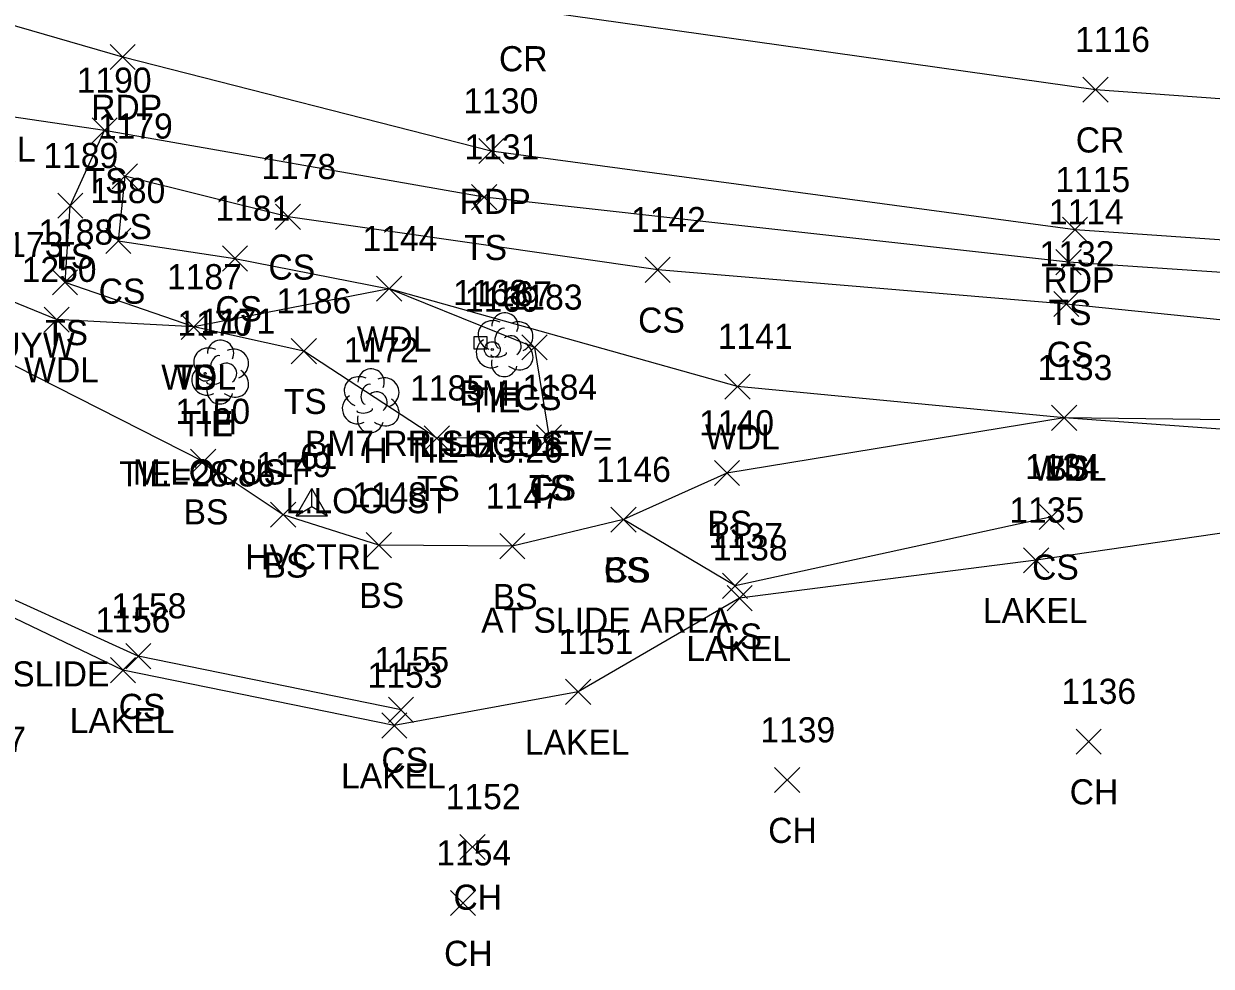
# Model space of a CAD drawing. Extents: x 1401404 to 1403982, y 557481 to 559873.
# Drawn here: x 1403353.7 to 1403448.2, y 558518.7 to 558593.7 of the extents above; entities that cross this region are included whole.
import ezdxf

# ---------------------------------------------------------------- set-up
doc = ezdxf.new("R2010")
doc.units = 0
for name, color, linetype in [('C_A', 7, 'Continuous'), ('C_C', 7, 'Continuous'), ('C_I', 7, 'Continuous'), ('CBP', 7, 'Continuous'), ('CPBM', 7, 'Continuous'), ('CPSM', 7, 'Continuous'), ('L_A', 7, 'Continuous'), ('L_C', 7, 'Continuous'), ('L_I', 7, 'Continuous'), ('L_TIC', 7, 'Continuous'), ('LAWA', 7, 'Continuous'), ('LAWE', 7, 'Continuous'), ('LELB', 7, 'Continuous'), ('LTD', 7, 'Continuous'), ('P_A', 7, 'Continuous'), ('P_I', 7, 'Continuous'), ('P_TIC', 7, 'Continuous'), ('PET', 7, 'Continuous'), ('PRC', 7, 'Continuous'), ('U_A', 7, 'Continuous'), ('U_I', 7, 'Continuous')]:
    doc.layers.add(name, color=color, linetype=linetype)

msp = doc.modelspace()

# ---------------------------------------------------------------- linework, layer by layer
at = {"layer": 'CBP'}
for centre, radius in [((1403391.006, 558567.757), 0.625), ((1403391.006, 558567.757), 0.0833), ((1403368.162, 558565.858), 0.625), ((1403368.162, 558565.858), 0.0833)]:
    msp.add_circle(centre, radius, dxfattribs=at)
at = {"layer": 'CPBM'}
for p, q in [((1403389.564, 558567.797), (1403389.564, 558568.797)), ((1403389.564, 558568.797), (1403390.564, 558568.797)), ((1403390.066, 558568.298), (1403390.066, 558568.298)), ((1403390.066, 558568.298), (1403390.066, 558568.298)), ((1403390.564, 558568.797), (1403390.564, 558567.797)), ((1403390.564, 558567.797), (1403389.564, 558567.797))]:
    msp.add_line(p, q, dxfattribs=at)
at = {"layer": 'CPSM'}
for p, q in [((1403375.408, 558554.533), (1403376.658, 558556.698)), ((1403377.908, 558554.533), (1403376.658, 558556.698)), ((1403376.659, 558555.254), (1403376.658, 558556.698)), ((1403375.408, 558554.533), (1403376.659, 558555.254)), ((1403376.659, 558555.254), (1403376.659, 558555.254)), ((1403376.659, 558555.254), (1403377.908, 558554.533)), ((1403375.408, 558554.533), (1403377.908, 558554.533))]:
    msp.add_line(p, q, dxfattribs=at)
at = {"layer": 'L_TIC'}
for points in [[(1403359.169, 558584.19), (1403361.169, 558586.19)], [(1403361.169, 558584.19), (1403359.169, 558586.19)], [(1403359.169, 558584.19), (1403361.169, 558586.19)], [(1403361.169, 558584.19), (1403359.169, 558586.19)], [(1403360.776, 558580.539), (1403362.776, 558582.539)], [(1403362.776, 558580.539), (1403360.776, 558582.539)], [(1403389.353, 558578.879), (1403391.353, 558580.879)], [(1403391.353, 558578.879), (1403389.353, 558580.879)], [(1403356.44, 558578.197), (1403358.44, 558580.197)], [(1403358.44, 558578.197), (1403356.44, 558580.197)], [(1403373.76, 558577.317), (1403375.76, 558579.317)], [(1403375.76, 558577.317), (1403373.76, 558579.317)], [(1403360.257, 558575.403), (1403362.257, 558577.403)], [(1403362.257, 558575.403), (1403360.257, 558577.403)], [(1403369.539, 558574.001), (1403371.539, 558576.001)], [(1403371.539, 558574.001), (1403369.539, 558576.001)], [(1403403.159, 558573.097), (1403405.159, 558575.097)], [(1403405.159, 558573.097), (1403403.159, 558575.097)], [(1403435.828, 558573.711), (1403437.828, 558575.711)], [(1403437.828, 558573.711), (1403435.828, 558575.711)], [(1403356.028, 558572.103), (1403358.028, 558574.103)], [(1403358.028, 558572.103), (1403356.028, 558574.103)], [(1403381.806, 558571.596), (1403383.806, 558573.596)], [(1403383.806, 558571.596), (1403381.806, 558573.596)], [(1403435.654, 558570.376), (1403437.654, 558572.376)], [(1403437.654, 558570.376), (1403435.654, 558572.376)], [(1403355.356, 558569.136), (1403357.356, 558571.136)], [(1403357.356, 558569.136), (1403355.356, 558571.136)], [(1403366.259, 558568.552), (1403368.259, 558570.552)], [(1403368.259, 558568.552), (1403366.259, 558570.552)], [(1403366.259, 558568.552), (1403368.259, 558570.552)], [(1403368.259, 558568.552), (1403366.259, 558570.552)], [(1403375.01, 558566.629), (1403377.01, 558568.629)], [(1403377.01, 558566.629), (1403375.01, 558568.629)], [(1403393.354, 558566.931), (1403395.354, 558568.931)], [(1403395.354, 558566.931), (1403393.354, 558568.931)], [(1403409.502, 558563.808), (1403411.502, 558565.808)], [(1403411.502, 558563.808), (1403409.502, 558565.808)], [(1403435.487, 558561.324), (1403437.487, 558563.324)], [(1403437.487, 558561.324), (1403435.487, 558563.324)], [(1403435.487, 558561.324), (1403437.487, 558563.324)], [(1403437.487, 558561.324), (1403435.487, 558563.324)], [(1403385.594, 558559.698), (1403387.594, 558561.698)], [(1403387.594, 558559.698), (1403385.594, 558561.698)], [(1403394.513, 558559.766), (1403396.513, 558561.766)], [(1403396.513, 558559.766), (1403394.513, 558561.766)], [(1403394.513, 558559.766), (1403396.513, 558561.766)], [(1403396.513, 558559.766), (1403394.513, 558561.766)], [(1403367.01, 558557.841), (1403369.01, 558559.841)], [(1403369.01, 558557.841), (1403367.01, 558559.841)], [(1403408.668, 558556.928), (1403410.668, 558558.928)], [(1403410.668, 558556.928), (1403408.668, 558558.928)], [(1403373.367, 558553.611), (1403375.367, 558555.611)], [(1403375.367, 558553.611), (1403373.367, 558555.611)], [(1403400.434, 558553.221), (1403402.434, 558555.221)], [(1403402.434, 558553.221), (1403400.434, 558555.221)], [(1403400.434, 558553.221), (1403402.434, 558555.221)], [(1403402.434, 558553.221), (1403400.434, 558555.221)], [(1403434.492, 558553.446), (1403436.492, 558555.446)], [(1403436.492, 558553.446), (1403434.492, 558555.446)], [(1403380.98, 558551.192), (1403382.98, 558553.192)], [(1403382.98, 558551.192), (1403380.98, 558553.192)], [(1403391.602, 558551.105), (1403393.602, 558553.105)], [(1403393.602, 558551.105), (1403391.602, 558553.105)], [(1403433.251, 558549.988), (1403435.251, 558551.988)], [(1403435.251, 558549.988), (1403433.251, 558551.988)], [(1403409.31, 558547.958), (1403411.31, 558549.958)], [(1403411.31, 558547.958), (1403409.31, 558549.958)], [(1403409.669, 558546.974), (1403411.669, 558548.974)], [(1403411.669, 558546.974), (1403409.669, 558548.974)], [(1403361.85, 558542.362), (1403363.85, 558544.362)], [(1403363.85, 558542.362), (1403361.85, 558544.362)], [(1403360.633, 558541.241), (1403362.633, 558543.241)], [(1403362.633, 558541.241), (1403360.633, 558543.241)], [(1403396.83, 558539.518), (1403398.83, 558541.518)], [(1403398.83, 558539.518), (1403396.83, 558541.518)], [(1403382.744, 558538.087), (1403384.744, 558540.087)], [(1403384.744, 558538.087), (1403382.744, 558540.087)], [(1403382.211, 558536.843), (1403384.211, 558538.843)], [(1403384.211, 558536.843), (1403382.211, 558538.843)], [(1403437.435, 558535.561), (1403439.435, 558537.561)], [(1403439.435, 558535.561), (1403437.435, 558537.561)], [(1403413.457, 558532.498), (1403415.457, 558534.498)], [(1403415.457, 558532.498), (1403413.457, 558534.498)], [(1403388.426, 558527.18), (1403390.426, 558529.18)], [(1403390.426, 558527.18), (1403388.426, 558529.18)], [(1403387.678, 558522.712), (1403389.678, 558524.712)], [(1403389.678, 558522.712), (1403387.678, 558524.712)]]:
    msp.add_lwpolyline(points, dxfattribs=at)
at = {"layer": 'LAWA'}
msp.add_lwpolyline([(1403486.896, 558558.65), (1403436.487, 558562.324), (1403410.502, 558564.808), (1403382.806, 558572.596), (1403367.259, 558569.552), (1403356.356, 558570.136), (1403328.829, 558581.386)], dxfattribs=at)
at = {"layer": 'LAWE'}
msp.add_lwpolyline([(1403696.339, 558534.541), (1403680.715, 558542.255), (1403669.402, 558548.582), (1403629.669, 558556.013), (1403603.5, 558551.349), (1403567.184, 558559.291), (1403520.129, 558560.765), (1403486.896, 558558.65), (1403434.251, 558550.988), (1403410.669, 558547.974), (1403397.83, 558540.518), (1403383.211, 558537.843), (1403361.633, 558542.241), (1403347.734, 558548.91), (1403330.859, 558557.202), (1403312.09, 558569.671), (1403266.361, 558595.501), (1403259.705, 558589.597), (1403257.895, 558590.945)], dxfattribs=at)
at = {"layer": 'LELB'}
for points in [[(1403567.19, 558568.672), (1403521.327, 558570.05), (1403484.768, 558571.485), (1403436.828, 558574.711), (1403390.353, 558579.879), (1403360.169, 558585.19), (1403345.928, 558587.285), (1403333.514, 558592.26), (1403317.515, 558600.618), (1403299.002, 558608.828), (1403282.939, 558617.965), (1403248.094, 558638.933), (1403217.119, 558660.936), (1403185.325, 558684.7), (1403148.792, 558715.456), (1403112.062, 558744.487), (1403074.233, 558776.659), (1403055.653, 558783.747), (1403043.183, 558796.215), (1403041.062, 558801.071)], [(1403395.513, 558560.766), (1403386.594, 558560.698), (1403376.01, 558567.629), (1403367.259, 558569.552), (1403357.028, 558573.103), (1403357.44, 558579.197), (1403360.169, 558585.19)], [(1403630.817, 558558.089), (1403605.037, 558560.568), (1403567.006, 558565.003), (1403521.817, 558567.095), (1403485.279, 558566.393), (1403436.654, 558571.376), (1403404.159, 558574.097), (1403374.76, 558578.317), (1403361.776, 558581.539), (1403361.257, 558576.403), (1403370.539, 558575.001)], [(1403725.577, 558523.668), (1403722.741, 558539.448), (1403706.557, 558549.474), (1403693.686, 558551.002), (1403674.49, 558552.834), (1403667, 558555.825), (1403630.817, 558558.089), (1403603.441, 558554.207), (1403567.497, 558561.8), (1403520.155, 558563.09), (1403486.237, 558561.719), (1403436.487, 558562.324), (1403409.668, 558557.928), (1403401.434, 558554.221), (1403392.602, 558552.105), (1403381.98, 558552.192), (1403374.367, 558554.611), (1403368.01, 558558.841), (1403339.846, 558573.137), (1403322.978, 558578.006)], [(1403370.539, 558575.001), (1403382.806, 558572.596)], [(1403394.354, 558567.931), (1403382.806, 558572.596)], [(1403383.744, 558539.087), (1403362.85, 558543.362), (1403348.357, 558549.947), (1403331.967, 558557.541), (1403320.969, 558571.115)], [(1403394.354, 558567.931), (1403395.513, 558560.766)], [(1403435.492, 558554.446), (1403410.31, 558548.958), (1403401.434, 558554.221)]]:
    msp.add_lwpolyline(points, dxfattribs=at)
at = {"layer": 'LTD'}
for p, q in [((1403391.966, 558568.192), (1403391.966, 558568.192)), ((1403391.966, 558568.192), (1403391.966, 558568.192)), ((1403369.347, 558566.014), (1403369.347, 558566.014)), ((1403369.347, 558566.014), (1403369.347, 558566.014)), ((1403381.314, 558563.731), (1403381.314, 558563.731)), ((1403381.314, 558563.731), (1403381.314, 558563.731))]:
    msp.add_line(p, q, dxfattribs=at)
for centre in [(1403392.013, 558569.626), (1403369.394, 558567.448), (1403381.361, 558565.165)]:
    msp.add_arc(centre, 1.047, 335.52715, 180.95627, dxfattribs=at)
for centre, major_axis, ratio, start_param, end_param in [((1403391.174, 558568.858), (1.21, -0.512), 0.895232, 1.570796, 4.712389), ((1403393.007, 558568.775), (-1.141, -0.483), 0.949671, 1.570796, 4.712389), ((1403391.757, 558568.65), (-0.208, -0.792), 0.645439, 3.141593, 6.283185), ((1403390.883, 558567.483), (0.584, -1.042), 0.959034, 3.141593, 6.283185), ((1403392.466, 558568.025), (-0.5, 0.667), 0.989748, 3.141593, 6.283185), ((1403392.966, 558567.358), (-1.09, 0.792), 0.841452, 1.570796, 4.712389), ((1403368.555, 558566.681), (1.21, -0.512), 0.895232, 1.570796, 4.712389), ((1403369.138, 558566.473), (-0.208, -0.792), 0.645439, 3.141593, 6.283185), ((1403370.388, 558566.598), (-1.141, -0.483), 0.949671, 1.570796, 4.712389), ((1403391.508, 558567.442), (-0.625, -0.083), 0.423636, 0, 3.141593), ((1403368.264, 558565.306), (0.584, -1.042), 0.959034, 3.141593, 6.283185), ((1403369.847, 558565.848), (-0.5, 0.667), 0.989748, 3.141593, 6.283185), ((1403391.966, 558566.692), (0.265, 1.061), 0.942809, 1.570796, 4.712389), ((1403370.347, 558565.181), (-1.09, 0.792), 0.841452, 1.570796, 4.712389), ((1403380.522, 558564.398), (1.21, -0.512), 0.895232, 1.570796, 4.712389), ((1403382.355, 558564.315), (-1.141, -0.483), 0.949671, 1.570796, 4.712389), ((1403369.347, 558564.514), (0.265, 1.061), 0.942809, 1.570796, 4.712389), ((1403368.889, 558565.264), (-0.625, -0.083), 0.423636, 0, 3.141593), ((1403381.105, 558564.189), (-0.208, -0.792), 0.645439, 3.141593, 6.283185), ((1403381.814, 558563.564), (-0.5, 0.667), 0.989748, 3.141593, 6.283185), ((1403380.231, 558563.023), (0.584, -1.042), 0.959034, 3.141593, 6.283185), ((1403382.314, 558562.898), (-1.09, 0.792), 0.841452, 1.570796, 4.712389), ((1403380.856, 558562.981), (-0.625, -0.083), 0.423636, 0, 3.141593), ((1403381.314, 558562.231), (0.265, 1.061), 0.942809, 1.570796, 4.712389)]:
    msp.add_ellipse(centre, major_axis=major_axis, ratio=ratio, start_param=start_param, end_param=end_param, dxfattribs=at)
at = {"layer": 'P_TIC'}
for points in [[(1403360.613, 558590.03), (1403362.613, 558592.03)], [(1403362.613, 558590.03), (1403360.613, 558592.03)], [(1403437.972, 558587.433), (1403439.972, 558589.433)], [(1403439.972, 558587.433), (1403437.972, 558589.433)], [(1403389.926, 558582.548), (1403391.926, 558584.548)], [(1403391.926, 558582.548), (1403389.926, 558584.548)], [(1403436.345, 558576.288), (1403438.345, 558578.288)], [(1403438.345, 558576.288), (1403436.345, 558578.288)]]:
    msp.add_lwpolyline(points, dxfattribs=at)
at = {"layer": 'PET'}
msp.add_lwpolyline([(1403567.323, 558571.161), (1403521.055, 558571.892), (1403485.08, 558573.953), (1403437.345, 558577.288), (1403390.926, 558583.548), (1403361.613, 558591.03), (1403321.823, 558602.545), (1403283.736, 558620.332), (1403244.193, 558645.3), (1403219.218, 558663.606), (1403205.442, 558672.119), (1403186.056, 558688.409), (1403150.644, 558718.107), (1403114.176, 558748.056), (1403076.198, 558780.032), (1403043.936, 558806.704), (1402997.13, 558841.767), (1402954.247, 558870.687), (1402915.87, 558893.532), (1402876.179, 558915.415), (1402801.328, 558955.205), (1402766.491, 558972.95)], dxfattribs=at)
at = {"layer": 'PRC'}
msp.add_lwpolyline([(1403567.874, 558582.773), (1403521.719, 558584.551), (1403486.229, 558585.007), (1403438.972, 558588.433), (1403393.102, 558594.896), (1403360.826, 558602.705), (1403288.915, 558631.603), (1403250.295, 558655.214), (1403225.89, 558672.347), (1403193.368, 558698.042), (1403157.152, 558726.964), (1403121.948, 558757.263), (1403083.224, 558789.984), (1403051.101, 558815.937), (1403004.274, 558851.49), (1402960.213, 558880.82), (1402921.635, 558903.817), (1402881.318, 558926.058), (1402807.323, 558964.726), (1402770.827, 558983.445)], dxfattribs=at)

# ---------------------------------------------------------------- texts
at = {"layer": 'C_A'}
for s, p in [('HVCTRL', (1403343.986, 558582.704)), ('BM', (1403388.381, 558563.298)), ('TIE', (1403389.085, 558562.757)), ('TIE', (1403366.241, 558560.858)), ('HVCTRL', (1403371.352, 558550.254))]:
    msp.add_text(s, height=2, dxfattribs=at).set_placement(p)
at = {"layer": 'C_C'}
for s, p in [('BM7 RR SIR ELEV=', (1403376.098, 558559.298)), ('TIE=43.26', (1403384.179, 558558.757)), ('TIE=28.86', (1403361.336, 558556.858))]:
    msp.add_text(s, height=2, dxfattribs=at).set_placement(p)
at = {"layer": 'C_I'}
for s, p in [('1168', (1403387.893, 558571.298)), ('1169', (1403388.825, 558570.757)), ('1170', (1403365.95, 558568.858)), ('61', (1403375.714, 558558.254))]:
    msp.add_text(s, height=2, dxfattribs=at).set_placement(p)
at = {"layer": 'L_A'}
for s, p in [('TS', (1403358.578, 558580.19)), ('TS', (1403358.578, 558580.19)), ('CS', (1403360.217, 558576.539)), ('TS', (1403388.763, 558574.879)), ('TS', (1403355.849, 558574.197)), ('CS', (1403373.201, 558573.317)), ('CS', (1403359.698, 558571.403)), ('CS', (1403368.98, 558570.001)), ('CS', (1403402.6, 558569.097)), ('TS', (1403435.237, 558569.711)), ('TS', (1403355.438, 558568.103)), ('WDL', (1403380.223, 558567.596)), ('CS', (1403435.095, 558566.376)), ('WDL', (1403353.774, 558565.136)), ('WDL', (1403364.676, 558564.552)), ('TS', (1403365.668, 558564.552)), ('TS', (1403374.419, 558562.629)), ('H', (1403391.399, 558563.192)), ('CS', (1403392.795, 558562.931)), ('H', (1403368.78, 558561.014)), ('WDL', (1403407.92, 558559.808)), ('H', (1403380.747, 558558.731)), ('WDL', (1403433.904, 558557.324)), ('BS', (1403434.928, 558557.324)), ('TS', (1403385.003, 558555.698)), ('TS', (1403393.922, 558555.766)), ('CS', (1403393.954, 558555.766)), ('BS', (1403366.451, 558553.841)), ('BS', (1403408.109, 558552.928)), ('BS', (1403372.808, 558549.611)), ('CS', (1403399.875, 558549.221)), ('BS', (1403399.875, 558549.221)), ('CS', (1403433.933, 558549.446)), ('BS', (1403380.421, 558547.192)), ('BS', (1403391.043, 558547.105)), ('LAKEL', (1403430.014, 558545.988)), ('CS', (1403408.751, 558543.958)), ('LAKEL', (1403406.433, 558542.974)), ('CS', (1403361.291, 558538.362)), ('LAKEL', (1403357.397, 558537.241)), ('LAKEL', (1403393.594, 558535.518)), ('CS', (1403382.185, 558534.087)), ('LAKEL', (1403378.974, 558532.843)), ('CH', (1403436.923, 558531.561)), ('CH', (1403412.945, 558528.498)), ('CH', (1403387.914, 558523.18)), ('CH', (1403387.167, 558518.712))]:
    msp.add_text(s, height=2, dxfattribs=at).set_placement(p)
at = {"layer": 'L_C'}
for s, p in [('L.LOCUST', (1403385.202, 558559.192)), ('M.LOCUST', (1403362.41, 558557.014)), ('L.LOCUST', (1403374.55, 558554.731)), ('AT SLIDE AREA', (1403390.119, 558545.221)), ('BEGIN HEAVY SLIDE', (1403333.948, 558540.947))]:
    msp.add_text(s, height=2, dxfattribs=at).set_placement(p)
at = {"layer": 'L_I'}
for s, p in [('1190', (1403357.956, 558588.19)), ('1190', (1403357.956, 558588.19)), ('1179', (1403359.642, 558584.539)), ('1131', (1403388.794, 558582.879)), ('1189', (1403355.306, 558582.197)), ('1178', (1403372.634, 558581.317)), ('1180', (1403359.045, 558579.403)), ('1181', (1403368.98, 558578.001)), ('1114', (1403435.269, 558577.711)), ('1142', (1403402.033, 558577.097)), ('1188', (1403354.902, 558576.103)), ('1144', (1403380.68, 558575.596)), ('1132', (1403434.528, 558574.376)), ('1250', (1403353.577, 558573.136)), ('1187', (1403365.133, 558572.552)), ('1187', (1403365.133, 558572.552)), ('1167', (1403389.793, 558571.192)), ('1183', (1403392.228, 558570.931)), ('1186', (1403373.829, 558570.629)), ('1171', (1403367.788, 558569.014)), ('1141', (1403408.943, 558567.808)), ('1172', (1403379.188, 558566.731)), ('1133', (1403434.361, 558565.324)), ('1133', (1403434.361, 558565.324)), ('1185', (1403384.468, 558563.698)), ('1184', (1403393.387, 558563.766)), ('1184', (1403393.387, 558563.766)), ('1150', (1403365.797, 558561.841)), ('1140', (1403407.456, 558560.928)), ('1149', (1403372.234, 558557.611)), ('1146', (1403399.253, 558557.221)), ('1146', (1403399.253, 558557.221)), ('1134', (1403433.366, 558557.446)), ('1148', (1403379.854, 558555.192)), ('1147', (1403390.476, 558555.105)), ('1135', (1403432.125, 558553.988)), ('1137', (1403408.184, 558551.958)), ('1138', (1403408.543, 558550.974)), ('1158', (1403360.724, 558546.362)), ('1156', (1403359.452, 558545.241)), ('1151', (1403396.271, 558543.518)), ('1155', (1403381.618, 558542.087)), ('1153', (1403381.085, 558540.843)), ('1136', (1403436.254, 558539.561)), ('1139', (1403412.323, 558536.498)), ('1157', (1403347.976, 558535.743)), ('1152', (1403387.3, 558531.18)), ('1154', (1403386.552, 558526.712))]:
    msp.add_text(s, height=2, dxfattribs=at).set_placement(p)
at = {"layer": 'P_A'}
for s, p in [('CR', (1403391.535, 558589.896)), ('RDP', (1403359.102, 558586.03)), ('CR', (1403437.405, 558583.433)), ('RDP', (1403388.414, 558578.548)), ('RDP', (1403434.833, 558572.288))]:
    msp.add_text(s, height=2, dxfattribs=at).set_placement(p)
at = {"layer": 'P_I'}
for s, p in [('1116', (1403437.358, 558591.433)), ('1130', (1403388.713, 558586.548)), ('1115', (1403435.786, 558580.288))]:
    msp.add_text(s, height=2, dxfattribs=at).set_placement(p)
at = {"layer": 'U_A'}
msp.add_text('GUYW', height=2, dxfattribs=at).set_placement((1403349.469, 558567.107))
at = {"layer": 'U_I'}
msp.add_text('1173', height=2, dxfattribs=at).set_placement((1403350.949, 558575.107))

doc.saveas('drawing.dxf')
